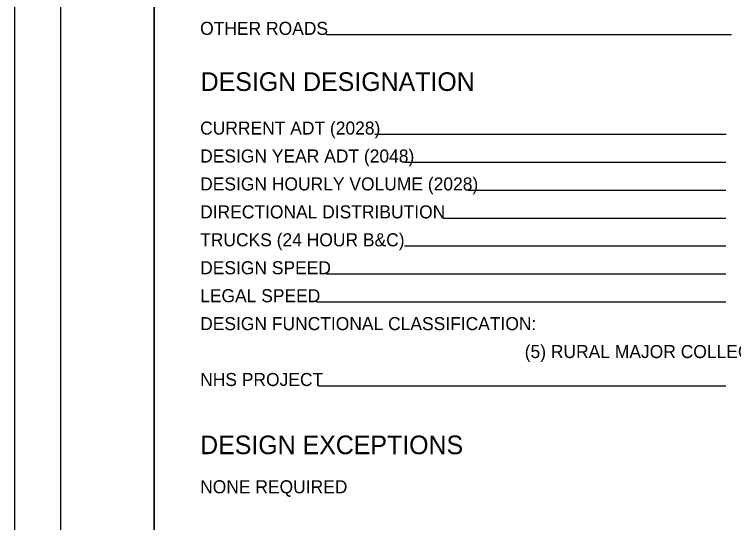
# Model space of a CAD drawing. Extents: x 0 to 34, y 0 to 22.
# Drawn here: x 0 to 7.72, y 5.64 to 11.1 of the extents above; entities that cross this region are included whole.
import ezdxf

# ---------------------------------------------------------------- set-up
doc = ezdxf.new("R2010")
doc.units = 0
for name, color, linetype in [('GM_X_County', 7, 'Continuous'), ('GM_X_Minor_Lake', 7, 'Continuous'), ('GM_X_Minor_Lake_Text', 7, 'Continuous'), ('GM_X_Minor_River_Text', 7, 'Continuous')]:
    doc.layers.add(name, color=color, linetype=linetype)

msp = doc.modelspace()

# ---------------------------------------------------------------- linework, layer by layer
at = {"layer": 'GM_X_County'}
msp.add_lwpolyline([(0, 0), (34, 0), (34, 22), (0, 22)], close=True, dxfattribs=at)
at = {"layer": 'GM_X_Minor_Lake_Text'}
for p, q in [((7.7, 10.8767), (3.3471, 10.8767)), ((7.6424, 9.8062), (3.871, 9.8062)), ((7.6368, 9.5062), (4.1885, 9.5062)), ((7.6368, 9.2062), (4.8723, 9.2062)), ((7.6368, 8.9062), (4.6037, 8.9062)), ((7.6368, 8.6062), (4.1885, 8.6062)), ((7.6368, 8.3062), (3.346, 8.3062)), ((7.6368, 8.0062), (3.2422, 8.0062)), ((7.6368, 7.1062), (3.2669, 7.1062))]:
    msp.add_line(p, q, dxfattribs=at)
at = {"layer": 'GM_X_Minor_River_Text'}
for points in [[(0.5, 21.5), (1.5, 21.5), (1.5, 0.5), (0.5, 0.5)], [(1.5, 21.5), (33.5, 21.5), (33.5, 0.5), (1.5, 0.5)]]:
    msp.add_lwpolyline(points, close=True, dxfattribs=at)

# ---------------------------------------------------------------- texts
at = {"layer": 'GM_X_Minor_Lake'}
for s, height, p in [('OTHER ROADS', 0.14, (1.9944, 10.8767)), ('CURRENT ADT (2028)', 0.14, (1.9944, 9.8062)), ('DESIGN YEAR ADT (2048)', 0.14, (1.9944, 9.5062)), ('DESIGN HOURLY VOLUME (2028)', 0.14, (1.9944, 9.2062)), ('DIRECTIONAL DISTRIBUTION', 0.14, (1.9944, 8.9062)), ('TRUCKS (24 HOUR B&C)', 0.14, (1.9944, 8.6062)), ('DESIGN SPEED', 0.14, (1.9944, 8.3062)), ('LEGAL SPEED', 0.14, (1.9944, 8.0062)), ('DESIGN FUNCTIONAL CLASSIFICATION:', 0.14, (1.9944, 7.7062)), ('                                                                   (5) RURAL MAJOR COLLECTOR', 0.14, (1.9944, 7.4062)), ('NHS PROJECT', 0.14, (1.9944, 7.1062)), ('DESIGN EXCEPTIONS', 0.2, (1.9944, 6.3744)), ('DESIGN EXCEPTIONS', 0.2, (1.9944, 6.3744)), ('NONE REQUIRED', 0.14, (1.9944, 5.9544))]:
    msp.add_text(s, height=height, dxfattribs=at).set_placement(p)
at = {"layer": 'GM_X_Minor_Lake_Text'}
msp.add_text('DESIGN DESIGNATION', height=0.2, dxfattribs=at).set_placement((2, 10.2747))

doc.saveas('drawing.dxf')
